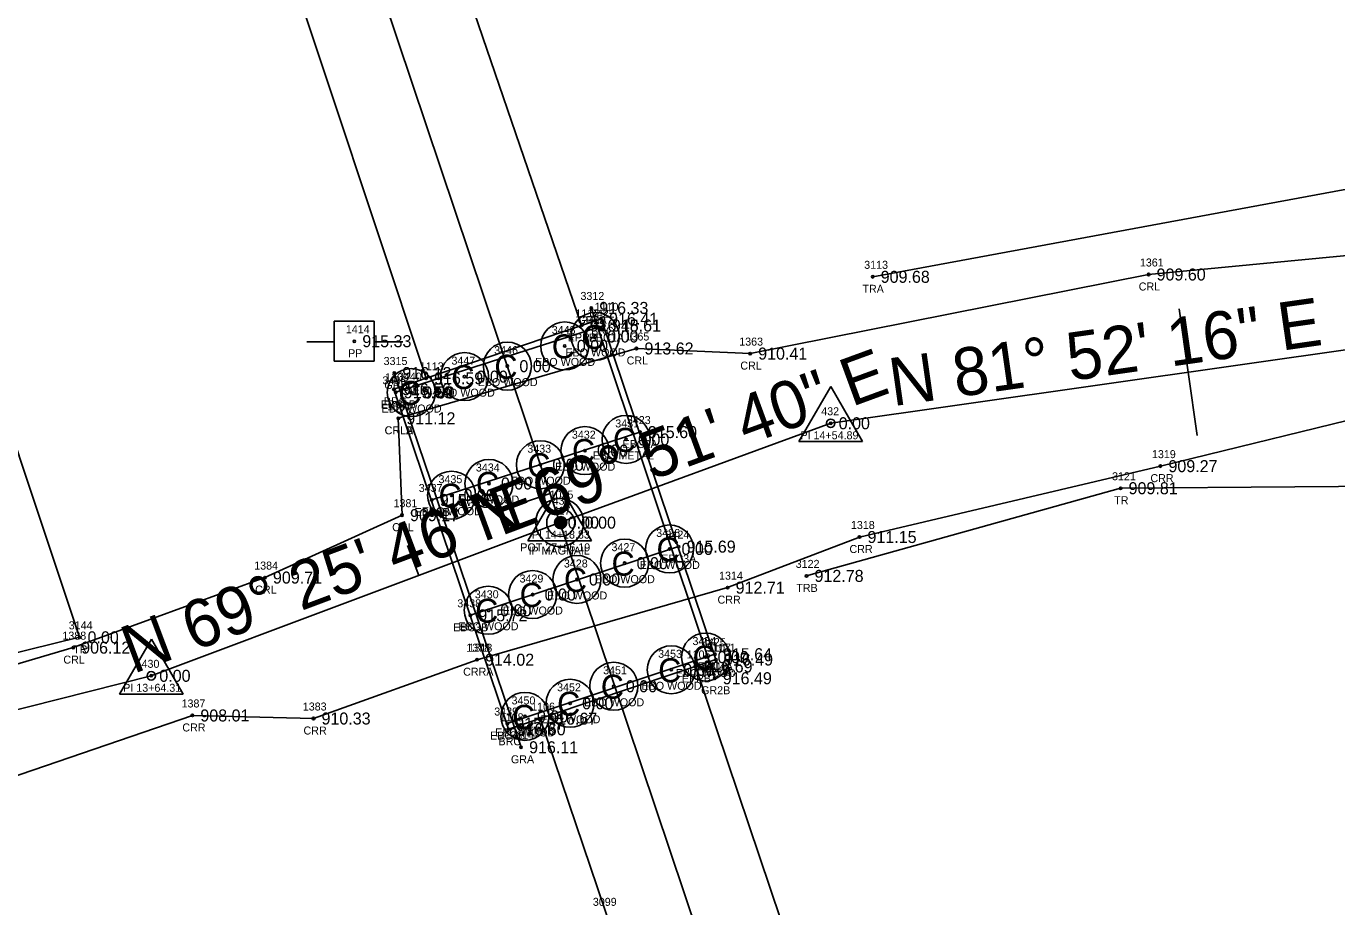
# Model space of a CAD drawing. Extents: x 1528109 to 1531398, y 1157799 to 1162548.
# Drawn here: x 1529705.3 to 1529869.1, y 1159860.9 to 1159971 of the extents above; entities that cross this region are included whole.
import ezdxf

# ---------------------------------------------------------------- set-up
doc = ezdxf.new("R2010")
doc.units = 0
for name, color, linetype in [('RD_EX_Bridge', 7, 'Continuous'), ('RD_EX_Bridge_txCode', 7, 'Continuous'), ('RD_EX_Driveway_txCode', 7, 'Continuous'), ('RD_EX_DV_Prop_txCode', 7, 'Continuous'), ('RD_EX_DV_PropPin', 7, 'Continuous'), ('RD_EX_GuardRail', 7, 'Continuous'), ('RD_EX_GuardRail_txCode', 7, 'Continuous'), ('RD_EX_H2O', 7, 'Continuous'), ('RD_EX_H2O_txCode', 7, 'Continuous'), ('RD_EX_Road', 7, 'Continuous'), ('RD_EX_Road_txCode', 7, 'Continuous'), ('RD_EX_TX_Bridge_ELEV', 7, 'Continuous'), ('RD_EX_TX_DV_Prop_ELEV', 7, 'Continuous'), ('RD_EX_TX_GuardRail_ELEV', 7, 'Continuous'), ('RD_EX_TX_H2O_ELEV', 7, 'Continuous'), ('RD_EX_TX_Road_ELEV', 7, 'Continuous'), ('RD_EX_TX_VEG_ELEV', 7, 'Continuous'), ('RD_EX_UT', 7, 'Continuous'), ('RD_EX_UT_txCode', 7, 'Continuous'), ('RD_EX_VEG', 7, 'Continuous'), ('RD_EX_VEG_txCode', 7, 'Continuous'), ('RD_HC_Cl', 7, 'Continuous'), ('RD_HC_Data', 7, 'Continuous'), ('RD_HC_Data_Tic', 7, 'Continuous'), ('RD_HC_Survey_ELEV', 7, 'Continuous'), ('RD_HC_txCode', 7, 'Continuous'), ('RD_SMD_Locator', 7, 'Continuous')]:
    doc.layers.add(name, color=color, linetype=linetype)

msp = doc.modelspace()

# ---------------------------------------------------------------- linework, layer by layer
at = {"layer": 'RD_EX_Bridge'}
for p, q in [((1529777.51, 1159933.61), (1529751.5, 1159925.26)), ((1529782.01, 1159920.29), (1529756, 1159911.8)), ((1529786.84, 1159905.97), (1529760.82, 1159897.38)), ((1529791.39, 1159892.52), (1529765.44, 1159883.85))]:
    msp.add_line(p, q, dxfattribs=at)
msp.add_lwpolyline([(1529791.51, 1159891.85), (1529765.59, 1159883.13), (1529751.26, 1159925.64), (1529777.16, 1159934.45), (1529791.51, 1159891.85)], dxfattribs=at)
for centre in [(1529776.42, 1159932.24), (1529772.62, 1159931.06), (1529760.09, 1159927.22), (1529765.45, 1159928.53), (1529753.44, 1159925.23), (1529780.28, 1159919.37), (1529775.14, 1159917.97), (1529769.57, 1159916.21), (1529763.14, 1159913.86), (1529758.47, 1159912.4), (1529785.71, 1159905.68), (1529780.09, 1159903.9), (1529774.14, 1159901.86), (1529768.6, 1159899.98), (1529763.05, 1159898.01), (1529790.21, 1159892.16), (1529785.92, 1159890.57), (1529778.75, 1159888.51), (1529773.29, 1159886.38), (1529767.64, 1159884.74)]:
    msp.add_circle(centre, 3, dxfattribs=at)
at = {"layer": 'RD_EX_DV_PropPin'}
for p, q in [((1529771.37, 1159908.78), (1529771.37, 1159909.17)), ((1529771.41, 1159908.67), (1529771.41, 1159909.27)), ((1529771.44, 1159908.6), (1529771.44, 1159909.34)), ((1529771.48, 1159908.55), (1529771.48, 1159909.4)), ((1529771.51, 1159908.5), (1529771.51, 1159909.45)), ((1529771.55, 1159908.46), (1529771.55, 1159909.49)), ((1529771.58, 1159908.42), (1529771.58, 1159909.52)), ((1529771.62, 1159908.39), (1529771.62, 1159909.55)), ((1529771.65, 1159908.36), (1529771.65, 1159909.58)), ((1529771.69, 1159908.34), (1529771.69, 1159909.61)), ((1529771.72, 1159908.32), (1529771.72, 1159909.63)), ((1529771.76, 1159908.3), (1529771.76, 1159909.65)), ((1529771.79, 1159908.28), (1529771.79, 1159909.66)), ((1529771.83, 1159908.26), (1529771.83, 1159909.68)), ((1529771.86, 1159908.25), (1529771.86, 1159909.69)), ((1529771.9, 1159908.24), (1529771.9, 1159909.7)), ((1529771.93, 1159908.23), (1529771.93, 1159909.71)), ((1529771.97, 1159908.22), (1529771.97, 1159909.72)), ((1529772, 1159908.22), (1529772, 1159909.73)), ((1529772.04, 1159908.21), (1529772.04, 1159909.73)), ((1529772.07, 1159908.21), (1529772.07, 1159909.73)), ((1529772.11, 1159908.21), (1529772.11, 1159909.73)), ((1529772.14, 1159908.21), (1529772.14, 1159909.73)), ((1529772.18, 1159908.21), (1529772.18, 1159909.73)), ((1529772.22, 1159908.22), (1529772.22, 1159909.73)), ((1529772.25, 1159908.22), (1529772.25, 1159909.72)), ((1529772.29, 1159908.23), (1529772.29, 1159909.71)), ((1529772.32, 1159908.24), (1529772.32, 1159909.7)), ((1529772.36, 1159908.25), (1529772.36, 1159909.69)), ((1529772.39, 1159908.26), (1529772.39, 1159909.68)), ((1529772.43, 1159908.28), (1529772.43, 1159909.66)), ((1529772.46, 1159908.3), (1529772.46, 1159909.65)), ((1529772.5, 1159908.32), (1529772.5, 1159909.63)), ((1529772.53, 1159908.34), (1529772.53, 1159909.61)), ((1529772.57, 1159908.36), (1529772.57, 1159909.58)), ((1529772.6, 1159908.39), (1529772.6, 1159909.55)), ((1529772.64, 1159908.42), (1529772.64, 1159909.52)), ((1529772.67, 1159908.46), (1529772.67, 1159909.49)), ((1529772.71, 1159908.5), (1529772.71, 1159909.45)), ((1529772.74, 1159908.55), (1529772.74, 1159909.4)), ((1529772.78, 1159908.6), (1529772.78, 1159909.34)), ((1529772.81, 1159908.67), (1529772.81, 1159909.27)), ((1529772.85, 1159908.78), (1529772.85, 1159909.17))]:
    msp.add_line(p, q, dxfattribs=at)
for radius in [1.75, 0.761]:
    msp.add_circle((1529772.11, 1159908.97), radius, dxfattribs=at)
at = {"layer": 'RD_EX_GuardRail'}
for p, q in [((1529775.93, 1159935.81), (1529791.36, 1159889.51)), ((1529767.16, 1159880.88), (1529751.32, 1159927.67))]:
    msp.add_line(p, q, dxfattribs=at)
at = {"layer": 'RD_EX_H2O'}
for points in [[(1529938.83, 1159943.68), (1529888.22, 1159944.07), (1529845.58, 1159939.99), (1529795.79, 1159930.1), (1529781.58, 1159930.74), (1529751.82, 1159922.01), (1529751.82, 1159922.01), (1529752.28, 1159909.9), (1529735.15, 1159902.1), (1529711.19, 1159893.34), (1529649.14, 1159875.01), (1529611.79, 1159867.22), (1529569.01, 1159857.16), (1529529.3, 1159848.12), (1529463.64, 1159832.32), (1529419.51, 1159820.53), (1529366.55, 1159808.3)], [(1529761.66, 1159891.83), (1529792.97, 1159900.84), (1529809.45, 1159907.17), (1529847.06, 1159916.03), (1529876.35, 1159923.19), (1529939.35, 1159928.81), (1529938.98, 1159943.55)], [(1529761.66, 1159891.83), (1529741.22, 1159884.48), (1529726.08, 1159884.86), (1529680.06, 1159869.1), (1529660.41, 1159865.23), (1529652.6, 1159863.07), (1529627.09, 1159856.91), (1529623.69, 1159853.06), (1529624.64, 1159834.46)]]:
    msp.add_lwpolyline(points, dxfattribs=at)
at = {"layer": 'RD_EX_Road'}
for points in [[(1529774.72, 1159933.62), (1529755.68, 1159989.25), (1529731.24, 1160061.98), (1529709.49, 1160126.43), (1529696.87, 1160163.6), (1529690.11, 1160182.42), (1529676.19, 1160223.82)], [(1529755.29, 1159927.01), (1529736.93, 1159982.35), (1529712.51, 1160054.89), (1529690.79, 1160119.37), (1529677.8, 1160158.1), (1529657.44, 1160217.45)], [(1530337.52, 1159156.44), (1530294.13, 1159166.93), (1530250.93, 1159177.7), (1530204.42, 1159191.5), (1530168.45, 1159204.97), (1530120.58, 1159231.54), (1530104.56, 1159243.15), (1530086.77, 1159257.61), (1530051.98, 1159290.88), (1530019.2, 1159326.18), (1529978.15, 1159378.31), (1529959.68, 1159408.2), (1529942.81, 1159442.34), (1529934.79, 1159460.88), (1529923.22, 1159491.09), (1529910.46, 1159527.95), (1529895.99, 1159570.93), (1529881.69, 1159613.98), (1529856.28, 1159690.67), (1529839.74, 1159739.71), (1529819.57, 1159800.04), (1529788.95, 1159890.99)], [(1530332.28, 1159136.67), (1530288.96, 1159147.06), (1530245.68, 1159158), (1530197.52, 1159172.18), (1530159.1, 1159186.57), (1530108.6, 1159214.89), (1530072.67, 1159242.37), (1530037.12, 1159276.96), (1530005.21, 1159311.5), (1529961.59, 1159366.88), (1529941.79, 1159398.29), (1529924.06, 1159434.11), (1529903.77, 1159484.39), (1529891.44, 1159520.8), (1529876.79, 1159564.7), (1529862.9, 1159606.82), (1529836.94, 1159684.29), (1529820.66, 1159733.09), (1529800.02, 1159794.4), (1529769.54, 1159884.46)]]:
    msp.add_lwpolyline(points, dxfattribs=at)
at = {"layer": 'RD_EX_UT'}
for p, q in [((1529748.81, 1159934.16), (1529743.81, 1159934.16)), ((1529743.81, 1159934.16), (1529743.81, 1159929.16)), ((1529748.81, 1159929.16), (1529748.81, 1159934.16)), ((1529740.38, 1159931.59), (1529743.85, 1159931.59)), ((1529748.74, 1159931.59), (1529752.38, 1159931.59)), ((1529743.81, 1159929.16), (1529748.81, 1159929.16))]:
    msp.add_line(p, q, dxfattribs=at)
at = {"layer": 'RD_EX_VEG'}
for points in [[(1529518.34, 1160217.08), (1529606.49, 1160211.39), (1529711.98, 1159894.63), (1529689.16, 1159889.01)], [(1529811.1, 1159939.7), (1529879.81, 1159952.4), (1529930.77, 1159958.28), (1529937.99, 1159919.25), (1529885.65, 1159913.6), (1529842.08, 1159913.27), (1529802.83, 1159902.31)]]:
    msp.add_lwpolyline(points, dxfattribs=at)
at = {"layer": 'RD_HC_Cl'}
for p, q in [((1529913.5, 1159487.74), (1529527.85, 1160635.77)), ((1529805.85, 1159921.39), (1529875.02, 1159931.27)), ((1529771.99, 1159908.98), (1529805.85, 1159921.39)), ((1529720.95, 1159889.82), (1529771.99, 1159908.98)), ((1529617.27, 1159863.55), (1529720.95, 1159889.82))]:
    msp.add_line(p, q, dxfattribs=at)
at = {"layer": 'RD_HC_Data'}
for p, q in [((1529801.88, 1159919.1), (1529805.85, 1159925.98)), ((1529805.85, 1159925.98), (1529809.82, 1159919.1)), ((1529801.88, 1159919.1), (1529809.82, 1159919.1)), ((1529768.02, 1159906.68), (1529772, 1159913.56)), ((1529772, 1159913.56), (1529775.96, 1159906.68)), ((1529768.02, 1159906.68), (1529775.96, 1159906.68)), ((1529716.98, 1159887.53), (1529720.96, 1159894.41)), ((1529720.96, 1159894.41), (1529724.92, 1159887.53)), ((1529716.98, 1159887.53), (1529724.92, 1159887.53))]:
    msp.add_line(p, q, dxfattribs=at)
for centre, radius in [((1529805.85, 1159921.39), 0.529), ((1529771.99, 1159908.98), 3), ((1529771.99, 1159908.98), 0.529), ((1529771.99, 1159908.98), 0.282), ((1529720.95, 1159889.82), 0.529)]:
    msp.add_circle(centre, radius, dxfattribs=at)
at = {"layer": 'RD_HC_Data_Tic'}
for p, q in [((1529850.51, 1159927.77), (1529849.38, 1159935.69)), ((1529850.51, 1159927.77), (1529851.64, 1159919.85)), ((1529770.78, 1159912.59), (1529766.99, 1159911.31)), ((1529754.37, 1159902.36), (1529752.96, 1159906.1))]:
    msp.add_line(p, q, dxfattribs=at)
at = {"layer": 'RD_SMD_Locator'}
for centre in [(1529811.1, 1159939.7), (1529845.58, 1159939.99), (1529775.93, 1159935.81), (1529774.72, 1159933.62), (1529777.16, 1159934.45), (1529777.51, 1159933.61), (1529746.32, 1159931.65), (1529776.42, 1159932.24), (1529772.62, 1159931.06), (1529781.58, 1159930.74), (1529795.79, 1159930.1), (1529765.45, 1159928.53), (1529751.32, 1159927.67), (1529755.29, 1159927.01), (1529760.09, 1159927.22), (1529751.26, 1159925.64), (1529751.5, 1159925.26), (1529753.44, 1159925.23), (1529751.82, 1159922.01), (1529751.82, 1159922.01), (1529782.01, 1159920.29), (1529805.85, 1159921.39), (1529780.28, 1159919.37), (1529775.14, 1159917.97), (1529769.57, 1159916.21), (1529847.06, 1159916.03), (1529763.14, 1159913.86), (1529756, 1159911.8), (1529758.47, 1159912.4), (1529842.08, 1159913.27), (1529752.28, 1159909.9), (1529771.99, 1159908.98), (1529771.99, 1159908.98), (1529772.11, 1159908.97), (1529809.45, 1159907.17), (1529785.71, 1159905.68), (1529786.84, 1159905.97), (1529780.09, 1159903.9), (1529735.15, 1159902.1), (1529802.83, 1159902.31), (1529774.14, 1159901.86), (1529792.97, 1159900.84), (1529768.6, 1159899.98), (1529760.82, 1159897.38), (1529763.05, 1159898.01), (1529711.98, 1159894.63), (1529711.19, 1159893.34), (1529790.21, 1159892.16), (1529791.39, 1159892.52), (1529761.66, 1159891.83), (1529761.66, 1159891.83), (1529785.92, 1159890.57), (1529788.95, 1159890.99), (1529791.51, 1159891.85), (1529791.51, 1159891.85), (1529720.95, 1159889.82), (1529791.36, 1159889.51), (1529778.75, 1159888.51), (1529773.29, 1159886.38), (1529726.08, 1159884.86), (1529741.22, 1159884.48), (1529767.64, 1159884.74), (1529769.54, 1159884.46), (1529765.44, 1159883.85), (1529765.59, 1159883.13), (1529767.16, 1159880.88)]:
    msp.add_circle(centre, 0.15, dxfattribs=at)

# ---------------------------------------------------------------- texts
at = {"layer": 'RD_EX_Bridge'}
for p in [(1529774.79, 1159930.68), (1529770.99, 1159929.5), (1529763.82, 1159926.96), (1529758.46, 1159925.66), (1529751.81, 1159923.67), (1529778.64, 1159917.81), (1529773.51, 1159916.41), (1529767.94, 1159914.65), (1529761.51, 1159912.3), (1529756.84, 1159910.84), (1529784.08, 1159904.12), (1529778.46, 1159902.34), (1529772.51, 1159900.3), (1529766.97, 1159898.42), (1529761.42, 1159896.45), (1529788.58, 1159890.6), (1529784.29, 1159889.01), (1529777.12, 1159886.95), (1529771.66, 1159884.82), (1529766.01, 1159883.18)]:
    msp.add_text('C', height=3, dxfattribs=at).set_placement(p)
at = {"layer": 'RD_EX_Bridge_txCode'}
for s, p in [('1110', (1529776.35, 1159935.45)), ('3422', (1529775.88, 1159934.61)), ('3448', (1529770.99, 1159932.56)), ('3449', (1529774.79, 1159933.74)), ('BRC', (1529775.91, 1159932.45)), ('EBC1A', (1529775.62, 1159931.61)), ('3446', (1529763.8, 1159930.03)), ('EBO WOOD', (1529772.7, 1159929.74)), ('3447', (1529758.46, 1159928.72)), ('EBO WOOD', (1529768.91, 1159928.56)), ('3436', (1529749.84, 1159926.26)), ('1109', (1529750.16, 1159926.64)), ('3440', (1529751.77, 1159926.73)), ('EBO WOOD', (1529761.73, 1159926.03)), ('EBO WOOD', (1529756.37, 1159924.72)), ('EBC1B', (1529749.63, 1159923.26)), ('EBO WOOD', (1529749.72, 1159922.73)), ('BRC', (1529750.01, 1159923.64)), ('3431', (1529778.93, 1159920.87)), ('3423', (1529780.38, 1159921.29)), ('3432', (1529773.51, 1159919.47)), ('3433', (1529767.94, 1159917.71)), ('EBC2A', (1529779.84, 1159918.29)), ('EBO METAL', (1529776.13, 1159916.87)), ('3434', (1529761.51, 1159915.36)), ('EBO WOOD', (1529771.43, 1159915.47)), ('3437', (1529754.37, 1159912.8)), ('3435', (1529756.84, 1159913.9)), ('EBO WOOD', (1529765.85, 1159913.71)), ('EBO WOOD', (1529759.42, 1159911.36)), ('EBC2B', (1529753.85, 1159909.8)), ('EBO WOOD', (1529754.75, 1159909.9)), ('3426', (1529784.05, 1159907.18)), ('3424', (1529785.21, 1159906.97)), ('3427', (1529778.46, 1159905.4)), ('3428', (1529772.51, 1159903.36)), ('EBO WOOD', (1529781.99, 1159903.18)), ('EBC3A', (1529784.67, 1159903.97)), ('3429', (1529766.97, 1159901.48)), ('EBO WOOD', (1529776.37, 1159901.4)), ('3430', (1529761.38, 1159899.51)), ('3438', (1529759.19, 1159898.38)), ('EBO WOOD', (1529770.42, 1159899.36)), ('EBO WOOD', (1529764.88, 1159897.48)), ('EBC3B', (1529758.67, 1159895.38)), ('EBO WOOD', (1529759.33, 1159895.51)), ('3454', (1529788.58, 1159893.66)), ('3425', (1529789.76, 1159893.52)), ('1107', (1529790.41, 1159892.85)), ('3453', (1529784.29, 1159892.07)), ('1111', (1529791.01, 1159892.85)), ('3451', (1529777.41, 1159890.01)), ('EBO WOOD', (1529786.49, 1159889.66)), ('EBC4A', (1529789.23, 1159890.52)), ('BRCA', (1529789.77, 1159889.85)), ('BRCB', (1529789.78, 1159889.85)), ('EBO WOOD', (1529782.21, 1159888.07)), ('3452', (1529771.66, 1159887.88)), ('3439', (1529763.81, 1159884.85)), ('3450', (1529765.97, 1159886.24)), ('EBO WOOD', (1529775.04, 1159886.01)), ('1108', (1529764.49, 1159884.13)), ('EBO WOOD', (1529769.57, 1159883.88)), ('EBC4B', (1529763.29, 1159881.85)), ('EBO WOOD', (1529763.92, 1159882.24)), ('BRC', (1529764.34, 1159881.13))]:
    msp.add_text(s, height=1, dxfattribs=at).set_placement(p)
at = {"layer": 'RD_EX_Driveway_txCode'}
msp.add_text('3099', height=1, dxfattribs=at).set_placement((1529776.13, 1159861.06))
at = {"layer": 'RD_EX_DV_Prop_txCode'}
for s, p in [('1025', (1529770.72, 1159911.97)), ('IP MAGNAIL', (1529768.09, 1159904.97))]:
    msp.add_text(s, height=1, dxfattribs=at).set_placement(p)
at = {"layer": 'RD_EX_GuardRail_txCode'}
for s, p in [('3312', (1529774.58, 1159936.81)), ('GR2A', (1529774.21, 1159933.81)), ('3315', (1529749.98, 1159928.67)), ('GRB', (1529750.07, 1159925.67)), ('3313', (1529790.01, 1159890.51)), ('GR2B', (1529789.66, 1159887.51)), ('3314', (1529765.81, 1159881.88)), ('GRA', (1529765.89, 1159878.88))]:
    msp.add_text(s, height=1, dxfattribs=at).set_placement(p)
at = {"layer": 'RD_EX_H2O_txCode'}
for s, p in [('1361', (1529844.49, 1159940.99)), ('CRL', (1529844.35, 1159937.99)), ('1365', (1529780.21, 1159931.74)), ('1363', (1529794.42, 1159931.1)), ('CRL', (1529780.35, 1159928.74)), ('CRL', (1529794.56, 1159928.1)), ('1380', (1529750.43, 1159923.01)), ('1367', (1529750.45, 1159923.01)), ('CRLA', (1529750.1, 1159920.01)), ('CRLB', (1529750.12, 1159920.01)), ('1319', (1529846, 1159917.03)), ('CRR', (1529845.81, 1159914.03)), ('1381', (1529751.22, 1159910.9)), ('CRL', (1529751.05, 1159907.9)), ('1318', (1529808.38, 1159908.17)), ('CRR', (1529808.2, 1159905.17)), ('1384', (1529733.81, 1159903.1)), ('1314', (1529791.9, 1159901.84)), ('CRL', (1529733.93, 1159900.1)), ('CRR', (1529791.71, 1159898.84)), ('1388', (1529709.84, 1159894.34)), ('CRL', (1529709.96, 1159891.34)), ('1378', (1529760.31, 1159892.83)), ('1313', (1529760.59, 1159892.83)), ('CRRA', (1529759.92, 1159889.83)), ('CRRA', (1529759.92, 1159889.83)), ('1387', (1529724.73, 1159885.86)), ('1383', (1529739.88, 1159885.48)), ('CRR', (1529724.83, 1159882.86)), ('CRR', (1529739.97, 1159882.48))]:
    msp.add_text(s, height=1, dxfattribs=at).set_placement(p)
at = {"layer": 'RD_EX_Road_txCode'}
for s, p in [('1112', (1529773.94, 1159934.62)), ('EPRA', (1529773, 1159931.62)), ('1113', (1529754.51, 1159928.01)), ('EPLA', (1529753.6, 1159925.01)), ('1105', (1529787.85, 1159891.99)), ('EPRB', (1529787.25, 1159888.99)), ('1106', (1529768.42, 1159885.46)), ('EPLB', (1529767.87, 1159882.46))]:
    msp.add_text(s, height=1, dxfattribs=at).set_placement(p)
at = {"layer": 'RD_EX_TX_Bridge_ELEV'}
for s, p in [('916.41', (1529778.16, 1159933.7)), ('915.61', (1529778.51, 1159932.86)), ('0.00', (1529774.12, 1159930.31)), ('0.00', (1529777.92, 1159931.49)), ('0.00', (1529766.95, 1159927.78)), ('0.00', (1529761.59, 1159926.47)), ('916.56', (1529752.26, 1159924.89)), ('915.59', (1529752.5, 1159924.51)), ('0.00', (1529754.94, 1159924.48)), ('0.00', (1529781.78, 1159918.62)), ('915.60', (1529783.01, 1159919.54)), ('0.00', (1529776.64, 1159917.22)), ('0.00', (1529771.07, 1159915.46)), ('0.00', (1529764.64, 1159913.11)), ('915.66', (1529757, 1159911.05)), ('0.00', (1529759.97, 1159911.65)), ('0.00', (1529787.21, 1159904.93)), ('915.69', (1529787.84, 1159905.22)), ('0.00', (1529781.59, 1159903.15)), ('0.00', (1529775.64, 1159901.11)), ('0.00', (1529770.1, 1159899.23)), ('0.00', (1529764.55, 1159897.26)), ('915.72', (1529761.82, 1159896.63)), ('0.00', (1529791.71, 1159891.41)), ('915.64', (1529792.39, 1159891.77)), ('916.49', (1529792.51, 1159891.1)), ('916.49', (1529792.51, 1159891.1)), ('0.00', (1529787.42, 1159889.82)), ('0.00', (1529780.25, 1159887.76)), ('0.00', (1529774.79, 1159885.63)), ('915.67', (1529766.44, 1159883.1)), ('0.00', (1529769.14, 1159883.99)), ('916.60', (1529766.59, 1159882.38))]:
    msp.add_text(s, height=1.5, dxfattribs=at).set_placement(p)
at = {"layer": 'RD_EX_TX_DV_Prop_ELEV'}
msp.add_text('0.00', height=1.5, dxfattribs=at).set_placement((1529775.11, 1159908.22))
at = {"layer": 'RD_EX_TX_GuardRail_ELEV'}
for s, p in [('916.33', (1529776.93, 1159935.06)), ('916.12', (1529752.32, 1159926.92)), ('916.49', (1529792.36, 1159888.76)), ('916.11', (1529768.16, 1159880.13))]:
    msp.add_text(s, height=1.5, dxfattribs=at).set_placement(p)
at = {"layer": 'RD_EX_TX_H2O_ELEV'}
for s, p in [('909.60', (1529846.58, 1159939.24)), ('913.62', (1529782.58, 1159929.99)), ('910.41', (1529796.79, 1159929.35)), ('911.12', (1529752.82, 1159921.26)), ('911.12', (1529752.82, 1159921.26)), ('909.27', (1529848.06, 1159915.28)), ('909.17', (1529753.28, 1159909.15)), ('911.15', (1529810.45, 1159906.42)), ('909.71', (1529736.15, 1159901.35)), ('912.71', (1529793.97, 1159900.09)), ('906.12', (1529712.19, 1159892.59)), ('914.02', (1529762.66, 1159891.08)), ('914.02', (1529762.66, 1159891.08)), ('908.01', (1529727.08, 1159884.11)), ('910.33', (1529742.22, 1159883.73))]:
    msp.add_text(s, height=1.5, dxfattribs=at).set_placement(p)
at = {"layer": 'RD_EX_TX_Road_ELEV'}
for s, p in [('916.48', (1529775.72, 1159932.87)), ('916.59', (1529756.29, 1159926.26)), ('916.69', (1529789.95, 1159890.24)), ('916.67', (1529770.54, 1159883.71))]:
    msp.add_text(s, height=1.5, dxfattribs=at).set_placement(p)
at = {"layer": 'RD_EX_TX_VEG_ELEV'}
for s, p in [('909.68', (1529812.1, 1159938.95)), ('909.81', (1529843.08, 1159912.52)), ('912.78', (1529803.83, 1159901.56)), ('0.00', (1529712.98, 1159893.88))]:
    msp.add_text(s, height=1.5, dxfattribs=at).set_placement(p)
at = {"layer": 'RD_EX_UT_txCode'}
for s, p in [('1414', (1529745.26, 1159932.65)), ('PP', (1529745.54, 1159929.65))]:
    msp.add_text(s, height=1, dxfattribs=at).set_placement(p)
at = {"layer": 'RD_EX_VEG_txCode'}
for s, p in [('3113', (1529810.04, 1159940.7)), ('TRA', (1529809.82, 1159937.7)), ('3121', (1529841.01, 1159914.27)), ('TR', (1529841.28, 1159911.27)), ('3122', (1529801.48, 1159903.31)), ('TRB', (1529801.56, 1159900.31)), ('3144', (1529710.63, 1159895.63)), ('TR', (1529711.19, 1159892.63))]:
    msp.add_text(s, height=1, dxfattribs=at).set_placement(p)
at = {"layer": 'RD_HC_Data'}
for s, rotation, p in [('N 81%%d 52\' 16" E', 8.1288, (1529813.61, 1159923.51)), ('N 69%%d 51\' 40" E', 20.139, (1529762.38, 1159906.52)), ('N 69%%d 25\' 46" E', 20.5706, (1529718.68, 1159890.03))]:
    msp.add_text(s, height=6, rotation=rotation, dxfattribs=at).set_placement(p)
at = {"layer": 'RD_HC_Survey_ELEV'}
for s, p in [('915.33', (1529747.32, 1159930.9)), ('0.00', (1529806.85, 1159920.64)), ('0.00', (1529772.99, 1159908.23)), ('0.00', (1529772.99, 1159908.23)), ('0.00', (1529721.95, 1159889.07))]:
    msp.add_text(s, height=1.5, dxfattribs=at).set_placement(p)
at = {"layer": 'RD_HC_txCode'}
for s, p in [('432', (1529804.67, 1159922.39)), ('PI 14+54.89', (1529802.07, 1159919.39)), ('431', (1529771.1, 1159911.21)), ('417', (1529771.1, 1159909.98)), ('PI 14+18.83', (1529768.5, 1159906.98)), ('POT 27+96.19', (1529767.06, 1159905.38)), ('430', (1529719.73, 1159890.82)), ('PI 13+64.31', (1529717.44, 1159887.82))]:
    msp.add_text(s, height=1, dxfattribs=at).set_placement(p)

doc.saveas('drawing.dxf')
